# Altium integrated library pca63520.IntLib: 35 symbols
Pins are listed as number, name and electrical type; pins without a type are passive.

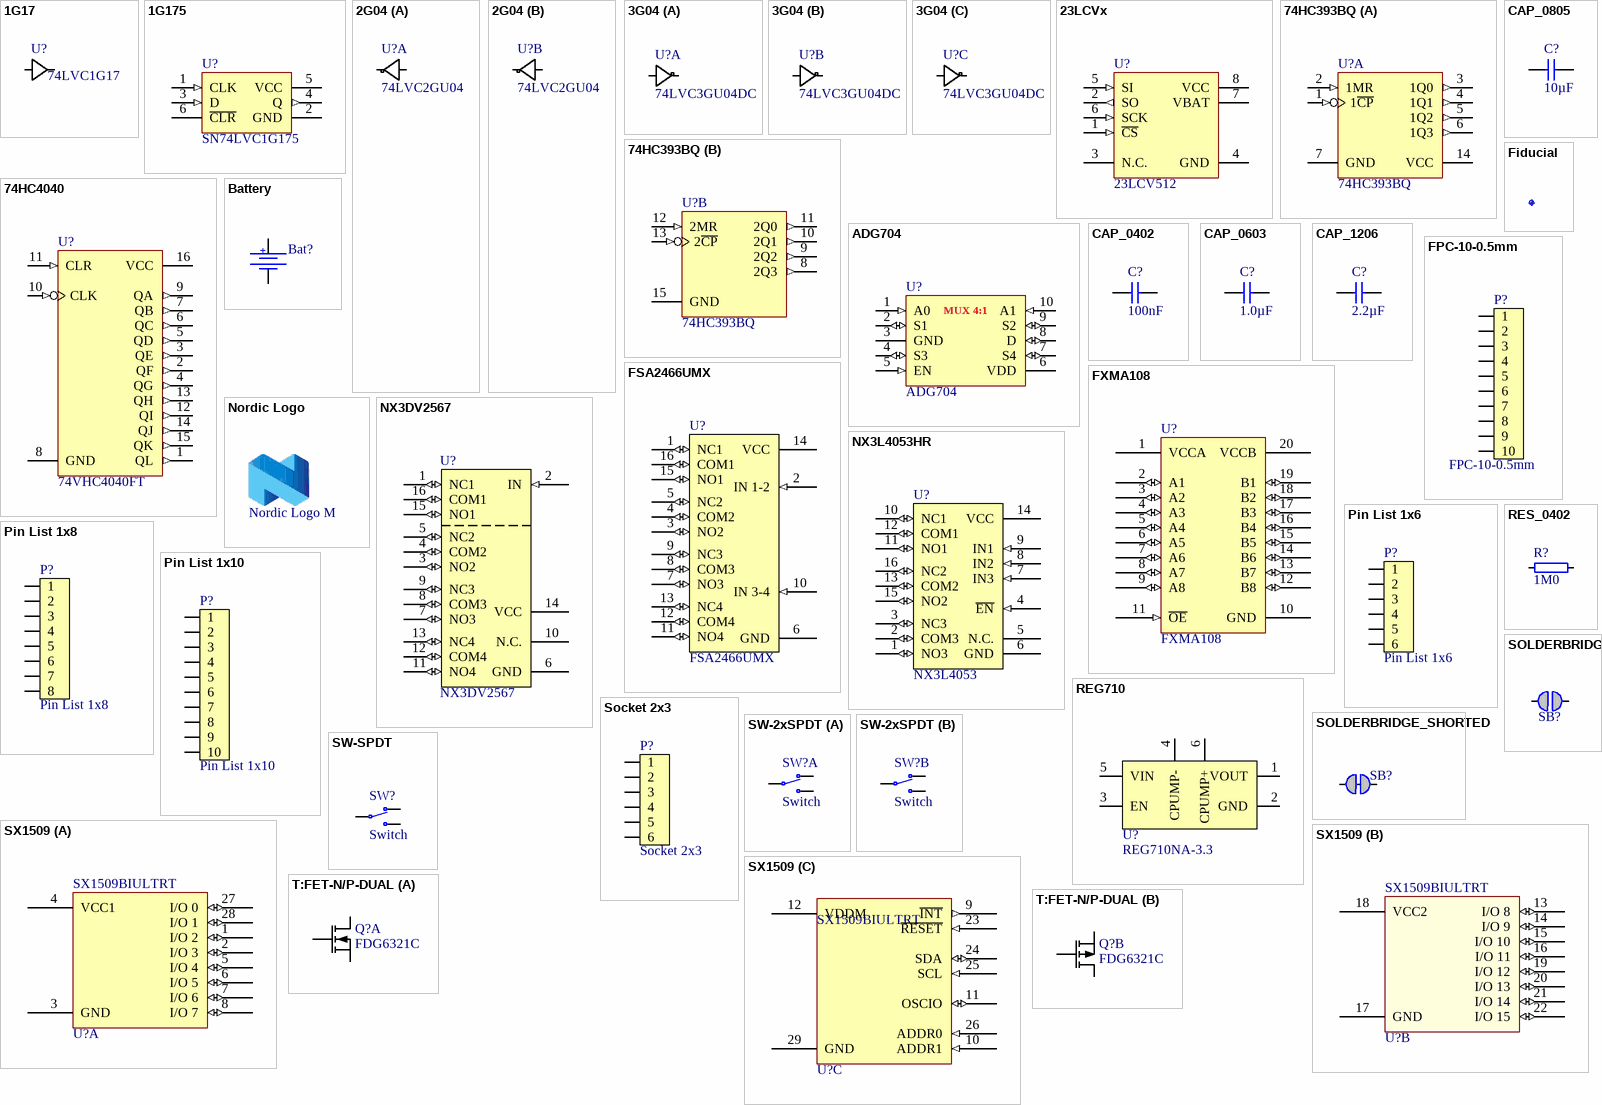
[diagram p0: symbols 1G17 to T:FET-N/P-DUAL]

## 1G17
designator U?, comment 74LVC1G17
Single schmitt-trigger buffer with standard push-pull output; Part Number: 74LVC1G17SE; Manufacturer: Diodes; 2nd source part number: 189-3834; Artikkelnr Noca: 15049066; Artikkelnr Simpro: N.A.
footprint SOT-353
pins: 1 N.C. hidden, 2 A, 3 GND hidden to GND, 4 Y, 5 VDD hidden to VDD_3V3

## 1G175
designator U?, comment SN74LVC1G175
Single D-Type Flip-Flop With Asynchronous Clear; Part Number: SN74LVC1G175DBVR; Manufacturer: Texas Instruments; Artikkelnr Noca: N.A.
footprint SOT95P280X145-6N
pins: 1 CLK (in), 2 GND (power), 3 D (in), 4 Q (out), 5 VCC (power), 6 ~{CLR}

## 2G04
designator U?, comment 74LVC2GU04
Dual Inverter; Manufacturer: NXP Semiconductors; Artikkelnr Noca: N.A.
footprint SOT65P210X100-6N
part A pins: 1 1A, 2 GND (power) hidden to GND, 6 1Y
part B pins: 3 2A, 4 2Y, 5 VCC (power) hidden to VDD_LF_XTAL

## 3G04
designator U?, comment 74LVC3GU04DC
Triple Inverter; Part Number: 74LVC3GU04DC,125; Manufacturer: NXP; Artikkelnr Noca: N.A.
footprint TSSOP50P310X90-8N
part A pins: 1 1A, 4 GND (power) hidden to GND, 7 1Y
part B pins: 3 2A, 5 2Y, 8 VCC (power) hidden to VCC_HF_XTAL
part C pins: 2 3Y, 6 3A

## 23LCVx
designator U?, comment 23LCV512
512 kbit SPI Serial SRAM with Battery Backup and SDI Interface; Part Number: 23LCV512-I/ST; Manufacturer: Microchip; 2nd source part number: 230-9514; Artikkelnr Noca: N.A.
footprint TSOP65P640X120-8N
pins: 1 ~{CS} (in), 2 SO (out), 3 N.C., 4 GND (power), 5 SI (in), 6 SCK (in), 7 VBAT (power), 8 VCC (power)

## 74HC393BQ
designator U?
Dual 4-bit binary ripple counter; Manufacturer: NXP Semiconductors; Artikkelnr Noca: N.A.
footprint QFN50P250X300X100_HS-15N
part A pins: 1 1~{CP} (in), 2 1MR (in), 3 1Q0 (out), 4 1Q1 (out), 5 1Q2 (out), 6 1Q3 (out), 7 GND (power), 14 VCC (power)
part B pins: 8 2Q3 (out), 9 2Q2 (out), 10 2Q1 (out), 11 2Q0 (out), 12 2MR (in), 13 2~{CP} (in), 15 GND (power)

## 74HC4040
designator U?, comment 74VHC4040FT
12-Stage Ripple Carry Binary Counter; Manufacturer: Toshiba; Artikkelnr Noca: N.A.
footprint TSOP65P640X110-16N
pins: 1 QL (out), 2 QF (out), 3 QE (out), 4 QG (out), 5 QD (out), 6 QC (out), 7 QB (out), 8 GND (power), 9 QA (out), 10 CLK (in), 11 CLR (in), 12 QI (out), 13 QH (out), 14 QJ (out), 15 QK (out), 16 VCC (power)

## ADG704
designator U?
IC MUX 4-CH 1.8/5.5V 10MSOP; Part Number: ADG704BRMZ; Manufacturer: Analog Devices; Note: 4:1 Analog MUX, ( RM-10, UMAX-10 ); Artikkelnr Noca: N.A.
footprint MSOP-10
pins: 1 A0 (in), 2 S1 (io), 3 GND (power), 4 S3 (io), 5 EN (in), 6 VDD (power), 7 S4 (io), 8 D (io), 9 S2 (io), 10 A1 (in)

## Battery
designator Bat?, comment Bat Holder CR1025  (value not drawn)
Bat Holder CR1025 SMD; Manufacturer: Keystone; Manufacturer Part Number: 3030; Artikkelnr Noca: N.A.
footprint CR1025_HOLDER_SMD
pins: 1, 2

## CAP_0402
designator C?, comment 100nF
Capacitor, X7R, ±10%; Part Number: C0402-100n; Note: 16V; Artikkelnr Noca: 20039200; Artikkelnr Simpro: N.A.
footprint CAPC1005X04L
pins: 1, 2

## CAP_0603
designator C?, comment 1.0µF
Capacitor, X7R, ±10%; Part Number: C0603-1µ0; Note: 16V; Artikkelnr Noca: 20039335; Artikkelnr Simpro: N.A.
footprint CAPC1608X06L
pins: 1, 2

## CAP_0805
designator C?, comment 10µF
Capacitor, X5R, ±10%; Part Number: C0805-10µ; Note: 16V; Artikkelnr Noca: 20039243; Artikkelnr Simpro: N.A.
footprint CAPC2012X11L
pins: 1, 2

## CAP_1206
designator C?, comment 2.2µF
Capacitor, X7R, ±10%; Part Number: C1206-2µ2; Note: 16V; Artikkelnr Noca: 20039142; Artikkelnr Simpro: N.A.
footprint CAPC3216X13L
pins: 1, 2

## Fiducial
designator Fid?, comment Fiducial mark  (value not drawn)
Part Number: Fid-Mark; Artikkelnr Noca: N.A.
footprint Fiducial

## FPC-10-0.5mm
designator P?
FFC/FPC Connector, Right-Angle, SMD, ZIF, Bottom Contacts, 10-way, Gold; Part Number: Molex 51441-1072; Manufacturer: Molex; Manufacturer Part Number: 51441-1072; 2nd source part number: 538-51441-1072; Artikkelnr Noca: N.A.
footprint Molex 51441-1072
pins: 1, 2, 3, 4, 5, 6, 7, 8, 9, 10

## FSA2466UMX
designator U?
Data / Audio Low-Voltage Dual DPDT Analog Switch; Manufacturer: Fairchild Semiconductor; 2nd source part number: 512-FSA2466UMX; Artikkelnr Noca: N.A.
footprint XQFN40P180X260X50-16N
pins: 1 NC1 (io), 2 IN 1-2 (in), 3 NO2 (io), 4 COM2 (io), 5 NC2 (io), 6 GND (power), 7 NO3 (io), 8 COM3 (io), 9 NC3 (io), 10 IN 3-4 (in), 11 NO4 (io), 12 COM4 (io), 13 NC4 (io), 14 VCC (power), 15 NO1 (io), 16 COM1 (io)

## FXMA108
designator U?
8-bit bidirectional voltage-level translator with auto-direction sensing; Part Number: FXMA108BQX; Manufacturer: Fairchild Semiconductor; 2nd source part number: 512-FXMA108BQX; Note: Translator, Bidirectional; Artikkelnr Noca: N.A.
footprint QFN50P450X250X80_HS-21N
pins: 1 VCCA (power), 2 A1 (io), 3 A2 (io), 4 A3 (io), 5 A4 (io), 6 A5 (io), 7 A6 (io), 8 A7 (io), 9 A8 (io), 10 GND (power), 11 ~{OE} (in), 12 B8 (io), 13 B7 (io), 14 B6 (io), 15 B5 (io), 16 B4 (io), 17 B3 (io), 18 B2 (io), 19 B1 (io), 20 VCCB (power)

## Nordic Logo
designator LOGO?, comment Nordic Logo M  (no BOM)
Nordic Logo, medium size; Artikkelnr Noca: N.A.
footprint NORDIC_LOGO_M

## NX3DV2567
designator U?
Low-ohmic four-pole double-throw analog switch; Part Number: NX3DV2567GU; Manufacturer: NXP Semiconductors; 2nd source part number: 771-NX3DV2567GU115; Artikkelnr Noca: N.A.
footprint XQFN40P180X260X50-16N
pins: 1 NC1 (io), 2 IN (in), 3 NO2 (io), 4 COM2 (io), 5 NC2 (io), 6 GND (power), 7 NO3 (io), 8 COM3 (io), 9 NC3 (io), 10 N.C., 11 NO4 (io), 12 COM4 (io), 13 NC4 (io), 14 VCC (power), 15 NO1 (io), 16 COM1 (io)

## NX3L4053HR
designator U?, comment NX3L4053
Triple low-ohmic single-pole double-throw analog switch; Part Number: NX3L4053HR; Manufacturer: NXP Semiconductors; 2nd source part number: 771-NX3L4053HR115; Artikkelnr Noca: 15079258; Artikkelnr Simpro: N.A.
footprint QFN50P300X300X50_HS-17N
pins: 1 NO3 (io), 2 COM3 (io), 3 NC3 (io), 4 ~{EN} (in), 5 N.C., 6 GND (power), 7 IN3 (in), 8 IN2 (in), 9 IN1 (in), 10 NC1 (io), 11 NO1 (io), 12 COM1 (io), 13 COM2 (io), 14 VCC (power), 15 NO2 (io), 16 NC2 (io), 17 PAD (power) hidden to GND

## Pin List 1x6
designator P?
Pin List 1x6, 2.54mm (100mil), SMD; Part Number: Pin List 1x6 SMD; Manufacturer: W-CON; Manufacturer Part Number: 1125-1106S0M116R2; 2nd source part number: TSM-106-01-L-SV-P-TR; Artikkelnr Noca: 55019252; Artikkelnr Simpro: N.A.
footprint LIST_1x6_SMD
pins: 1, 2, 3, 4, 5, 6

## Pin List 1x8
designator P?
Pin List 1x8, 2.54mm (100mil), SMD; Part Number: Pin List 1x8 SMD; Manufacturer: W-CON; Manufacturer Part Number: 1125-1108S0M116R2; 2nd source part number: TSM-108-01-L-SV-P-TR; Artikkelnr Noca: 55010006; Artikkelnr Simpro: N.A.
footprint LIST_1x8_SMD
pins: 1, 2, 3, 4, 5, 6, 7, 8

## Pin List 1x10
designator P?
Pin List 1x10, 2.54mm (100mil), SMD; Part Number: Pin List 1x10 SMD; Manufacturer: W-CON; Manufacturer Part Number: 1125-1110S0M116R2; 2nd source part number: TSM-110-01-L-SV-P-TR; Artikkelnr Noca: 55019254; Artikkelnr Simpro: N.A.
footprint LIST_1x10_SMD
pins: 1, 2, 3, 4, 5, 6, 7, 8, 9, 10

## REG710
designator U?, comment REG710NA-3.3
IC MULTI CONFG 3.3V 30MA SOT23-6; Manufacturer: Texas Instruments; Manufacturer Part Number: REG710NA-3.3/250; 2nd source part number: 296-12135-1-ND; Note: 60mA, 5.0V, Buck/Boost Charge Pump in ThinSOT-23; Artikkelnr Noca: N.A.
footprint SOT95P280X145-6N
pins: 1 VOUT, 2 GND, 3 EN, 4 CPUMP-, 5 VIN, 6 CPUMP+

## RES_0402
designator R?, comment 1M0
Resistor, ±1%, 0.063W; Part Number: R0402-1M0; Note: Chip Res 1%; Artikkelnr Noca: 27049145; Artikkelnr Simpro: N.A.; Value Ohm: 1000000
footprint RESC1005X04L
pins: 1, 2

## Socket 2x3
designator P?
Socket 2x3, 2.54mm (100mil), SMD; Part Number: Socket 2x3 SMD Bottom; Manufacturer: W-CON; Manufacturer Part Number: 2171-203MS0CUNR1; 2nd source part number: SSM-103-F-DV-P-TR; Artikkelnr Noca: 55019255; Artikkelnr Simpro: N.A.
footprint SOCKET_2x3_SMD-2.54mm-bottom
pins: 1, 2, 3, 4, 5, 6

## SOLDERBRIDGE
designator SB?, comment Solderbridge  (value not drawn)  (no BOM)
Artikkelnr Noca: N.A.
footprint Solderbridge
pins: 1 0, 2 1

## SOLDERBRIDGE_SHORTED
designator SB?, comment Solderbridge  (value not drawn)  (net tie, no BOM)
Shorted Solderbridge; Part Number: Solderbridge Shorted; Artikkelnr Noca: N.A.
footprint Solderbridge_Shorted
pins: 1 0, 2 1

## SW-2xSPDT
designator SW?, comment Switch
SMD slide Switch 2xSPDT; Part Number: CAS-D20TA; Manufacturer: Copal Electronics Inc; Artikkelnr Noca: N.A.
footprint CAS-D20A
part A pins: 1 N.O, 2 COM, 3 N.C
part B pins: 4 N.O, 5 COM, 6 N.C

## SW-SPDT
designator SW?, comment Switch
SMD slide Switch (ON-ON); Part Number: CJS-1200TA; Manufacturer: Copal Electronics Inc; Artikkelnr Noca: 50019068; Artikkelnr Simpro: N.A.
footprint CJS-120xA
pins: 1 N.C, 2 COM, 3 N.O

## SX1509
designator U?, comment SX1509BIULTRT
IC GPIO EXPANDER I2C 16CH 28QFN; Manufacturer: Semtech Corporation; Artikkelnr Noca: N.A.
footprint QFN40P400X400X60_HS-29N
part A pins: 1 I/O 2 (io), 2 I/O 3 (io), 3 GND (power), 4 VCC1 (power), 5 I/O 4 (io), 6 I/O 5 (io), 7 I/O 6 (io), 8 I/O 7 (io), 27 I/O 0 (io), 28 I/O 1 (io)
part B pins: 13 I/O 8 (io), 14 I/O 9 (io), 15 I/O 10 (io), 16 I/O 11 (io), 17 GND (power), 18 VCC2 (power), 19 I/O 12 (io), 20 I/O 13 (io), 21 I/O 14 (io), 22 I/O 15 (io)
part C pins: 9 ~{INT} (out), 10 ADDR1 (in), 11 OSCIO (io), 12 VDDM (power), 23 ~{RESET} (in), 24 SDA (io), 25 SCL (in), 26 ADDR0 (in), 29 GND (power)

## T:FET-N/P-DUAL
designator Q?, comment FDG6321C
Fairchild, FDG6321C, Dual N & P Channel Digital FET; 2nd source part number: FDG6321CCT-ND; Artikkelnr Noca: 35029089; Artikkelnr Simpro: N.A.
footprint SOT65P210X100-6N
part A pins: 1 S1, 2 G1, 6 D1
part B pins: 3 D2, 4 S2, 5 G2

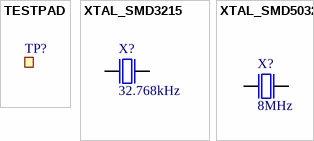
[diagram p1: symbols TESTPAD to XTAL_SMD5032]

## TESTPAD
designator TP?, comment Ø1.0mm,SMD  (value not drawn)  (no BOM)
1.0mm circular SMD testpad; Part Number: TP_SMD_Ø1.0MM; Manufacturer: Nordic Semiconductor; Artikkelnr Noca: N.A.
footprint TP_SMD_Ø1.0mm
pins: 1

## XTAL_SMD3215
designator X?, comment 32.768kHz
EPSON TOYOCOM - FC-135 32.768KHZ ±20PPM,9.0PF - CRYSTAL, SM, WATCH; Part Number: XTAL_FC-135 32.768k; 2nd source part number: 127-8037; Note: XTAL SMD 32.768kHz, 3215; Artikkelnr Noca: 22019091; Artikkelnr Simpro: N.A.
footprint XTAL_3215
pins: 1 inp, 2 out

## XTAL_SMD5032
designator X?, comment 8MHz
XTAL SMD 5032, 8MHz, Cl=18pF, Tol: ±30ppm, Stab: ±30ppm; Part Number: XTAL_SMD5032_8MHz_18pF_TXC; Manufacturer: TXC Corporation; Manufacturer Part Number: 7B-8.000MAAJ-T; 2nd source part number: 717-7B-8.000MAAJ-T; Note: XTAL SMD 8MHz; Artikkelnr Noca: N.A.
footprint BT-XTAL_5032
pins: 1 inp, 2 GND hidden to GND, 3 out, 4 GND hidden to GND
